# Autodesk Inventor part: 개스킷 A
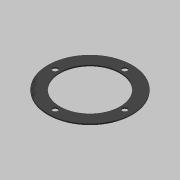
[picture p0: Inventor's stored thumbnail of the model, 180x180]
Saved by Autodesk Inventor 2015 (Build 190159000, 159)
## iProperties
Created: 2019-02
Part Number: 개스킷 A
Material: 고무
Document SubType Name: Modeling
Designer: mduedu
Density: 0.93 g/cm^3
Appearance: 고무 - 검은색 - 버전 1.1
Mass: 1.69384 g
Surface Area: 40.7622 cm^2
Volume: 1.82134 cm^3
Author: mduedu
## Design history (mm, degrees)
sketch "스케치1"
  geometry: C1 r 35 at (0, 0); C2 r 25 at (0, 0); 1 further point
  constraints: 2 centre point, 2 coincident
  dimensions: "d0" = 70 diameter of C1; "d1" = 50 diameter of C2
extrude "돌출1" new body sketch "스케치1" distance "d2" = 1; taper "d3" = 0 deg
sketch "스케치2" dims "d4" = 58
  geometry: 3 further points
  constraints: 2 vertical alignment, 1 coincident, 2 other
hole "구멍1" sketch "스케치2" at (0, 29) diameter "d5" = 4.5; stored, may be unused: countersink angle "d9" = 90 deg, drill point angle "d11" = 118 deg; dims "d6" = 6, "d7" = 4, "d8" = 2, "d10" = 8
node "솔리드1"
pattern_circular "원형 패턴1" dims angle "d13" = 360 deg
